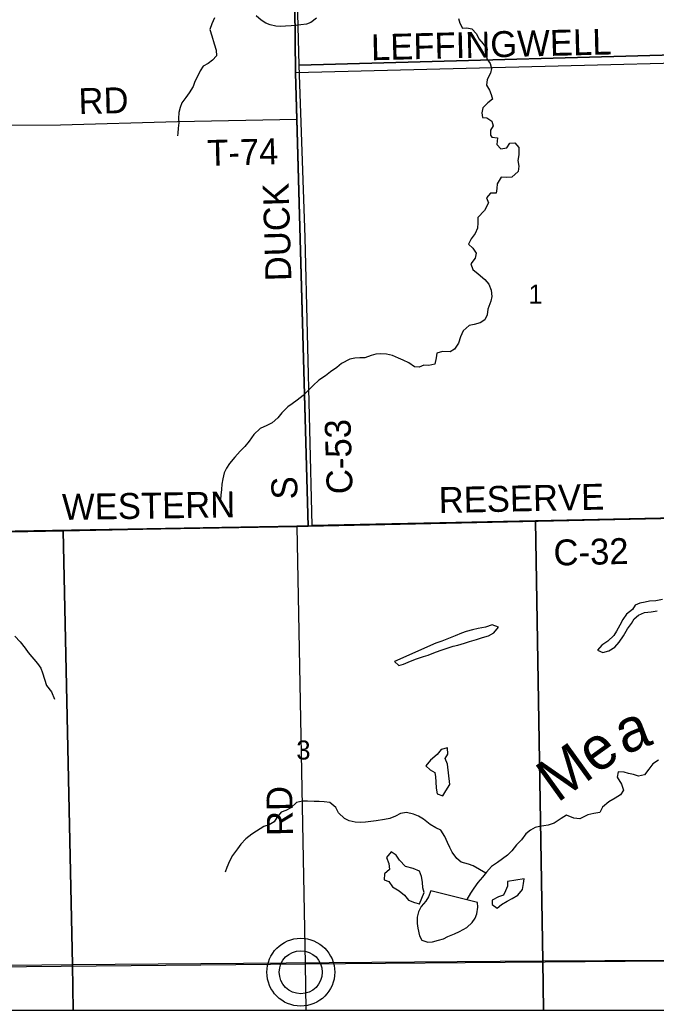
# Model space of a CAD drawing. Extents: x 0 to 34, y 0 to 22.
# Drawn here: x 6.705 to 8.101, y 14.007 to 16.179 of the extents above; entities that cross this region are included whole.
import ezdxf

# ---------------------------------------------------------------- set-up
doc = ezdxf.new("R2010")
doc.units = 0
for name, color, linetype in [('GM_X_Corporation', 7, 'Continuous'), ('GM_X_County_Road', 7, 'Continuous'), ('GM_X_County_Road_Text', 7, 'Continuous'), ('GM_X_Minor_Lake', 7, 'Continuous'), ('GM_X_Minor_River', 7, 'Continuous'), ('GM_X_Minor_River_Text', 7, 'Continuous'), ('GM_X_Section_Text', 7, 'Continuous'), ('GM_X_Township_Road', 7, 'Continuous'), ('GM_X_Township_Road_Text', 7, 'Continuous'), ('GM_X_Unincorporated', 7, 'Continuous'), ('GM_X_Unincorporated_Location', 7, 'Continuous')]:
    doc.layers.add(name, color=color, linetype=linetype)

msp = doc.modelspace()

# ---------------------------------------------------------------- linework, layer by layer
at = {"layer": 'GM_X_Corporation'}
for points in [[(7.283, 17.3071), (7.2872, 17.1772), (7.2911, 17.0516), (7.2943, 16.935), (7.2998, 16.7507), (7.3046, 16.5913), (7.3049, 16.5704), (7.3097, 16.0633), (7.3129, 15.9614), (7.3375, 15.0689), (8.3803, 15.0917), (8.8365, 15.1033), (9.7895, 15.1275), (9.7895, 20.2375)], [(2.9895, 20.1176), (2.9895, 14.989), (3.1061, 14.9902), (3.7218, 15.0051), (5.1362, 15.0301), (5.7825, 15.0418), (6.0746, 15.0468), (7.3134, 15.0684), (7.3375, 15.0689), (7.3129, 15.9614), (7.3097, 16.0633), (7.3049, 16.5704), (7.3046, 16.5913), (7.2998, 16.7507), (7.2943, 16.935), (7.2911, 17.0516), (7.2872, 17.1772), (7.283, 17.3071)]]:
    msp.add_lwpolyline(points, dxfattribs=at)
for points in [[(8.3006, 17.1406), (8.3266, 16.1074), (7.3183, 16.0795), (7.3111, 16.3358), (7.2941, 16.9623), (7.2894, 17.115)], [(7.3183, 16.0795), (8.3266, 16.1074), (8.3505, 15.0912), (7.8364, 15.0804), (7.3467, 15.0701), (7.331, 15.7019)], [(3.7367, 14.0069), (9.7895, 14.0069), (9.7895, 15.1275), (8.8365, 15.1033), (8.3803, 15.0917), (7.3375, 15.0689), (7.3134, 15.0684), (6.0746, 15.0468), (5.7825, 15.0418), (5.1362, 15.0301), (3.7218, 15.0051), (3.7359, 14.0555)], [(8.9404, 15.1037), (8.9421, 14.1205), (7.8527, 14.1143), (7.8364, 15.0804), (8.3505, 15.0912)], [(7.8364, 15.0804), (7.8527, 14.1143), (6.8205, 14.106), (6.8006, 15.0584), (6.9076, 15.0603), (7.3467, 15.0701)], [(6.8006, 15.0584), (6.8205, 14.106), (5.8061, 14.0956), (5.789, 15.0408), (6.0694, 15.0457), (6.4885, 15.0527)], [(5.8075, 14.0069), (6.8225, 14.0069), (6.8205, 14.106), (5.8061, 14.0956)], [(6.8225, 14.0069), (7.8543, 14.0069), (7.8527, 14.1143), (6.8205, 14.106)], [(7.8543, 14.0069), (8.9421, 14.0069), (8.9421, 14.1205), (7.8527, 14.1143)]]:
    msp.add_lwpolyline(points, close=True, dxfattribs=at)
at = {"layer": 'GM_X_County_Road'}
for p, q in [((7.3136, 15.0678), (7.3377, 15.0683)), ((7.332, 14.1088), (7.3136, 15.0678)), ((7.3335, 14.0069), (7.332, 14.1088))]:
    msp.add_line(p, q, dxfattribs=at)
for points in [[(7.3099, 16.0628), (7.3051, 16.5699), (7.3048, 16.5907), (7.3, 16.7502), (7.2945, 16.9345), (7.2913, 17.051), (7.2874, 17.1766), (7.2832, 17.3066), (7.2801, 17.4169), (7.2766, 17.5196), (7.2753, 17.5759), (7.2469, 19.0552)], [(9.7895, 16.1277), (8.8082, 16.1011), (7.3099, 16.0628)], [(7.3377, 15.0683), (7.3131, 15.9608), (7.3099, 16.0628)], [(7.3377, 15.0683), (8.3805, 15.0912), (8.8367, 15.1028)], [(3.722, 15.0045), (5.1364, 15.0296), (5.7827, 15.0412), (6.0748, 15.0463), (7.3136, 15.0678)], [(7.332, 14.1088), (8.3836, 14.1171), (9.7895, 14.1254)], [(4.8042, 14.0781), (5.8006, 14.0939), (7.332, 14.1088)]]:
    msp.add_lwpolyline(points, dxfattribs=at)
at = {"layer": 'GM_X_Minor_Lake'}
for points in [[(8.1152, 14.9074), (8.1005, 14.9048), (8.0868, 14.9038), (8.077, 14.9021), (8.0653, 14.9), (8.0552, 14.8956), (8.0493, 14.886), (8.0362, 14.8755), (8.0281, 14.8639), (8.0219, 14.8513), (8.0142, 14.8386), (8.0083, 14.829), (7.9953, 14.8166), (7.9822, 14.8076), (7.9725, 14.7964), (7.984, 14.7913), (7.9975, 14.7954), (8.0103, 14.8032), (8.0199, 14.8144), (8.0299, 14.8283), (8.0387, 14.8433), (8.0472, 14.8548), (8.0531, 14.8652), (8.0628, 14.8733), (8.0756, 14.8789), (8.0903, 14.8807), (8.1035, 14.8825)], [(7.527, 14.7717), (7.5367, 14.7631), (7.5472, 14.766), (7.5626, 14.7724), (7.5758, 14.7776), (7.5909, 14.7824), (7.6014, 14.7856), (7.6134, 14.7904), (7.6277, 14.7956), (7.6405, 14.8), (7.6556, 14.8053), (7.6658, 14.8077), (7.6809, 14.8122), (7.6918, 14.8154), (7.7072, 14.8199), (7.7204, 14.8243), (7.7332, 14.828), (7.7452, 14.8343), (7.7552, 14.847), (7.7411, 14.8521), (7.7268, 14.8473), (7.711, 14.8439), (7.6981, 14.841), (7.6842, 14.8377), (7.6744, 14.8341), (7.6601, 14.8281), (7.6417, 14.8206), (7.6312, 14.8162), (7.618, 14.8118)], [(7.618, 14.8118), (7.527, 14.7717)], [(7.6437, 14.5467), (7.6386, 14.5592), (7.6441, 14.5688), (7.6431, 14.5821), (7.6299, 14.5784), (7.6206, 14.568), (7.606, 14.5555), (7.5957, 14.5428), (7.6057, 14.5343), (7.616, 14.5284), (7.617, 14.5189), (7.6175, 14.5079), (7.6186, 14.4939), (7.6207, 14.4814), (7.6333, 14.4767), (7.6399, 14.4882), (7.6487, 14.5016)], [(7.6487, 14.5016), (7.6437, 14.5467)], [(7.5921, 14.2647), (7.5896, 14.2753), (7.5883, 14.2878), (7.5865, 14.3003), (7.5818, 14.3116), (7.568, 14.3178), (7.5512, 14.3224), (7.5381, 14.3358), (7.5307, 14.3471), (7.5196, 14.3541), (7.5096, 14.3418), (7.5151, 14.3286), (7.5161, 14.3157), (7.505, 14.306), (7.5048, 14.2931), (7.5151, 14.2891), (7.5229, 14.2774), (7.5371, 14.269), (7.5494, 14.2593), (7.5579, 14.2481), (7.5713, 14.2434), (7.5821, 14.2405)], [(7.5921, 14.2647), (7.5896, 14.2753), (7.5883, 14.2878), (7.5865, 14.3003), (7.5818, 14.3116), (7.568, 14.3178), (7.5512, 14.3224), (7.5381, 14.3358), (7.5307, 14.3471), (7.5196, 14.3541), (7.5096, 14.3418), (7.5151, 14.3286), (7.5161, 14.3157), (7.505, 14.306), (7.5048, 14.2931), (7.5151, 14.2891), (7.5229, 14.2774), (7.5371, 14.269), (7.5494, 14.2593), (7.5579, 14.2481), (7.5713, 14.2434), (7.5831, 14.2402)], [(7.7754, 14.2894), (7.7748, 14.2788), (7.7709, 14.2684), (7.7661, 14.2589), (7.7552, 14.2552), (7.7413, 14.2485), (7.7415, 14.239), (7.7522, 14.2305), (7.7619, 14.2386), (7.7747, 14.2461), (7.7856, 14.252), (7.7976, 14.2591), (7.8079, 14.2714), (7.8103, 14.2851), (7.8113, 14.2947)], [(7.8113, 14.2947), (7.7754, 14.2894)], [(7.6072, 14.2688), (7.6017, 14.2558), (7.5962, 14.2462), (7.5858, 14.2346), (7.5796, 14.2223), (7.5772, 14.2112), (7.5771, 14.1972), (7.5784, 14.1866), (7.5817, 14.1703), (7.5872, 14.1605), (7.6006, 14.1558), (7.6108, 14.1568), (7.624, 14.1605), (7.6345, 14.1637), (7.6443, 14.1684), (7.6589, 14.174), (7.6698, 14.1796), (7.6856, 14.1886), (7.6979, 14.1991), (7.7045, 14.2087), (7.7081, 14.2183), (7.7101, 14.2331), (7.7096, 14.2434)], [(7.5821, 14.2405), (7.5921, 14.2647)], [(7.7096, 14.2434), (7.6072, 14.2688)]]:
    msp.add_lwpolyline(points, dxfattribs=at)
at = {"layer": 'GM_X_Minor_River'}
for points in [[(7.3563, 16.1828), (7.3438, 16.1732), (7.3344, 16.1697), (7.3214, 16.1685), (7.3116, 16.1669), (7.3002, 16.1664), (7.288, 16.1652), (7.2766, 16.1643), (7.2667, 16.165), (7.2541, 16.1683), (7.2446, 16.1717), (7.2346, 16.1788), (7.2239, 16.1878)], [(7.1323, 16.1833), (7.1263, 16.1703), (7.1222, 16.1578), (7.1265, 16.1441), (7.1316, 16.1263), (7.1356, 16.113), (7.1364, 16.1005), (7.1282, 16.0909), (7.1183, 16.0836), (7.1077, 16.0778), (7.101, 16.0675), (7.0961, 16.0576), (7.0894, 16.0438), (7.0853, 16.0332), (7.0767, 16.0194), (7.0692, 16.0091), (7.0609, 15.9972), (7.0568, 15.9873), (7.0539, 15.9763), (7.0536, 15.963), (7.0537, 15.9535), (7.0523, 15.9417), (7.052, 15.931), (7.0513, 15.925)], [(7.6678, 16.1819), (7.6702, 16.172), (7.6764, 16.161), (7.6862, 16.1619), (7.6965, 16.1597), (7.7069, 16.1484), (7.7119, 16.1374), (7.7219, 16.1264), (7.7308, 16.1143), (7.7286, 16.1041), (7.7298, 16.0934), (7.7371, 16.0836), (7.7399, 16.0722), (7.7377, 16.0623), (7.7306, 16.0482)], [(7.7306, 16.0482), (7.7288, 16.036), (7.7354, 16.0251), (7.7396, 16.0152), (7.7424, 16.005), (7.7318, 15.9973), (7.7213, 15.9862), (7.7191, 15.9751), (7.7203, 15.9653), (7.7298, 15.9642), (7.7405, 15.9571), (7.744, 15.9468), (7.738, 15.9369), (7.7381, 15.9266), (7.7407, 15.9221)], [(7.7407, 15.9221), (7.7532, 15.9204), (7.7519, 15.906), (7.7608, 15.8963), (7.7733, 15.8984), (7.7799, 15.9088), (7.7909, 15.9098), (7.8002, 15.8989), (7.7997, 15.8833), (7.7977, 15.8708), (7.7998, 15.8579), (7.7985, 15.8465), (7.7844, 15.834), (7.7734, 15.8331), (7.7609, 15.834), (7.7524, 15.8198), (7.7515, 15.8095), (7.7501, 15.7988), (7.7376, 15.7994), (7.7291, 15.7889), (7.7335, 15.778), (7.7243, 15.7607), (7.7102, 15.746), (7.7097, 15.7343), (7.7095, 15.7225), (7.7044, 15.7106), (7.6955, 15.699), (7.6893, 15.6868), (7.6993, 15.6782), (7.706, 15.6673), (7.7039, 15.6567), (7.6947, 15.6439), (7.699, 15.6319), (7.711, 15.6222), (7.7256, 15.6096), (7.7338, 15.5991), (7.7393, 15.5863), (7.7407, 15.5723), (7.7382, 15.562), (7.7317, 15.5447), (7.7308, 15.5322), (7.725, 15.5211), (7.7152, 15.5144), (7.702, 15.5108), (7.6911, 15.509), (7.6781, 15.497), (7.6722, 15.4836), (7.6676, 15.4698), (7.6591, 15.4568), (7.649, 15.4513), (7.6327, 15.4517), (7.6198, 15.4484), (7.6189, 15.4378), (7.6158, 15.4237), (7.6025, 15.4211), (7.5912, 15.4221), (7.5814, 15.4173), (7.5708, 15.4183), (7.5585, 15.4268), (7.5459, 15.433), (7.5356, 15.4373), (7.5226, 15.4432), (7.5093, 15.4456), (7.4971, 15.4465), (7.4861, 15.4459), (7.476, 15.4427), (7.462, 15.4379), (7.4514, 15.438), (7.4401, 15.4371), (7.4295, 15.4346), (7.4107, 15.4255), (7.4003, 15.4169), (7.3865, 15.4068), (7.3756, 15.3986), (7.3614, 15.3885), (7.3491, 15.3772), (7.3365, 15.3648), (7.3268, 15.3555), (7.3134, 15.3447), (7.3025, 15.3372), (7.2928, 15.3302), (7.2801, 15.3174), (7.2712, 15.3063), (7.259, 15.295), (7.2469, 15.2891), (7.2326, 15.2831), (7.2185, 15.2696), (7.2085, 15.2553), (7.1985, 15.243), (7.1889, 15.2329), (7.177, 15.2198), (7.1655, 15.2063), (7.1585, 15.1959), (7.1537, 15.1859), (7.1502, 15.1722), (7.1485, 15.1607), (7.1476, 15.1493), (7.1463, 15.1368), (7.1457, 15.1273)], [(6.6944, 14.827), (6.7056, 14.8151), (6.7172, 14.8012), (6.7238, 14.7915), (6.744, 14.7672), (6.751, 14.757), (6.7549, 14.7472), (6.7594, 14.7329), (6.7634, 14.7189), (6.7743, 14.7054), (6.7814, 14.6892)], [(8.1062, 14.5555), (8.0942, 14.5476), (8.0853, 14.5353), (8.0753, 14.523), (8.0625, 14.5204), (8.0518, 14.5237), (8.0408, 14.5261), (8.0309, 14.529), (8.0176, 14.5299), (8.0159, 14.5181), (8.0253, 14.5023), (8.0297, 14.4894), (8.0231, 14.4791), (8.0111, 14.4716), (7.9976, 14.4642), (7.9838, 14.4525), (7.978, 14.4402), (7.9647, 14.4381), (7.9515, 14.4352), (7.9335, 14.4269), (7.9206, 14.4281), (7.9049, 14.4347), (7.893, 14.4272), (7.8776, 14.4174), (7.8644, 14.4126), (7.8455, 14.41), (7.8357, 14.4075), (7.8256, 14.402), (7.8155, 14.3939), (7.8055, 14.3804), (7.7948, 14.3695), (7.7848, 14.3564), (7.7751, 14.3471), (7.7643, 14.339), (7.7534, 14.3308), (7.7399, 14.3218), (7.7292, 14.3094), (7.7199, 14.2986), (7.7099, 14.287), (7.701, 14.2747), (7.694, 14.2636), (7.6858, 14.2493)], [(7.7274, 14.3073), (7.7001, 14.3237), (7.6895, 14.3273), (7.6738, 14.3319), (7.6638, 14.3397), (7.6534, 14.3532), (7.6486, 14.3634), (7.6431, 14.3747), (7.6376, 14.3882), (7.6286, 14.4014), (7.6179, 14.4069), (7.6056, 14.4142), (7.5906, 14.4257), (7.5799, 14.4327), (7.5685, 14.4371), (7.5532, 14.4406), (7.54, 14.4381), (7.5291, 14.4322), (7.5167, 14.4277), (7.5054, 14.4253), (7.4873, 14.4219), (7.4752, 14.4205), (7.4634, 14.4195), (7.4517, 14.4189), (7.4411, 14.4191), (7.4278, 14.4219), (7.4175, 14.427), (7.4043, 14.4397), (7.3981, 14.4513), (7.385, 14.4621), (7.3728, 14.4642), (7.3622, 14.4647), (7.3508, 14.4645), (7.3364, 14.4657), (7.3251, 14.4655), (7.3119, 14.4626), (7.3, 14.4506), (7.2891, 14.4451), (7.2785, 14.4415), (7.2693, 14.4295), (7.263, 14.4199), (7.2521, 14.4136), (7.2405, 14.41), (7.2247, 14.3994), (7.2139, 14.3932), (7.2008, 14.3827), (7.1904, 14.3714), (7.1826, 14.361), (7.1716, 14.346), (7.165, 14.3334), (7.1592, 14.32), (7.1556, 14.3093)]]:
    msp.add_lwpolyline(points, dxfattribs=at)
at = {"layer": 'GM_X_Township_Road'}
msp.add_lwpolyline([(7.3131, 15.9608), (7.0513, 15.9556), (6.7947, 15.9481), (6.5899, 15.9475), (6.3611, 15.9388), (6.1369, 15.9328), (6.0463, 15.9282), (5.9481, 15.9181), (5.8864, 15.9123), (5.7783, 15.8996), (5.7151, 15.8908), (5.6504, 15.8839), (5.1195, 15.8708)], dxfattribs=at)
at = {"layer": 'GM_X_Unincorporated'}
for radius in [0.0744, 0.0472]:
    msp.add_circle((7.3216, 14.0902), radius, dxfattribs=at)
at = {"layer": 'GM_X_Unincorporated_Location'}
msp.add_line((7.3216, 14.0902), (7.3216, 14.0902), dxfattribs=at)

# ---------------------------------------------------------------- texts
at = {"layer": 'GM_X_County_Road_Text'}
for s, height, rotation, p in [('LEFFINGWELL', 0.056818, 1.3972, (7.4763, 16.0905)), ('DUCK', 0.05682, 91.699, (7.3011, 15.6067)), ('C-53', 0.05682, 91.714, (7.4355, 15.1395)), ('S', 0.0568, 91.2447, (7.3145, 15.1277)), ('WESTERN', 0.05682, 0.8747, (6.7982, 15.0822)), ('RESERVE', 0.05682, 1.2385, (7.6247, 15.0972)), ('C-32', 0.05682, 1.3726, (7.8767, 14.982)), ('RD', 0.05682, 90.9891, (7.3045, 14.3894))]:
    msp.add_text(s, height=height, rotation=rotation, dxfattribs=at).set_placement(p)
at = {"layer": 'GM_X_Minor_River_Text'}
for s, height, rotation, p in [('a', 0.0947, 20.7084, (8.0312, 14.5666)), ('Me', 0.09473, 35.7093, (7.8841, 14.4604))]:
    msp.add_text(s, height=height, rotation=rotation, dxfattribs=at).set_placement(p)
at = {"layer": 'GM_X_Section_Text'}
for s, p in [('1', (7.821, 15.5566)), ('3', (7.3118, 14.5566))]:
    msp.add_text(s, height=0.0419, rotation=0, dxfattribs=at).set_placement(p)
at = {"layer": 'GM_X_Township_Road_Text'}
for s, rotation, p in [('RD', 1.4826, (6.8346, 15.9722)), ('T-74', 1.415, (7.1168, 15.8587))]:
    msp.add_text(s, height=0.05682, rotation=rotation, dxfattribs=at).set_placement(p)

doc.saveas('drawing.dxf')
